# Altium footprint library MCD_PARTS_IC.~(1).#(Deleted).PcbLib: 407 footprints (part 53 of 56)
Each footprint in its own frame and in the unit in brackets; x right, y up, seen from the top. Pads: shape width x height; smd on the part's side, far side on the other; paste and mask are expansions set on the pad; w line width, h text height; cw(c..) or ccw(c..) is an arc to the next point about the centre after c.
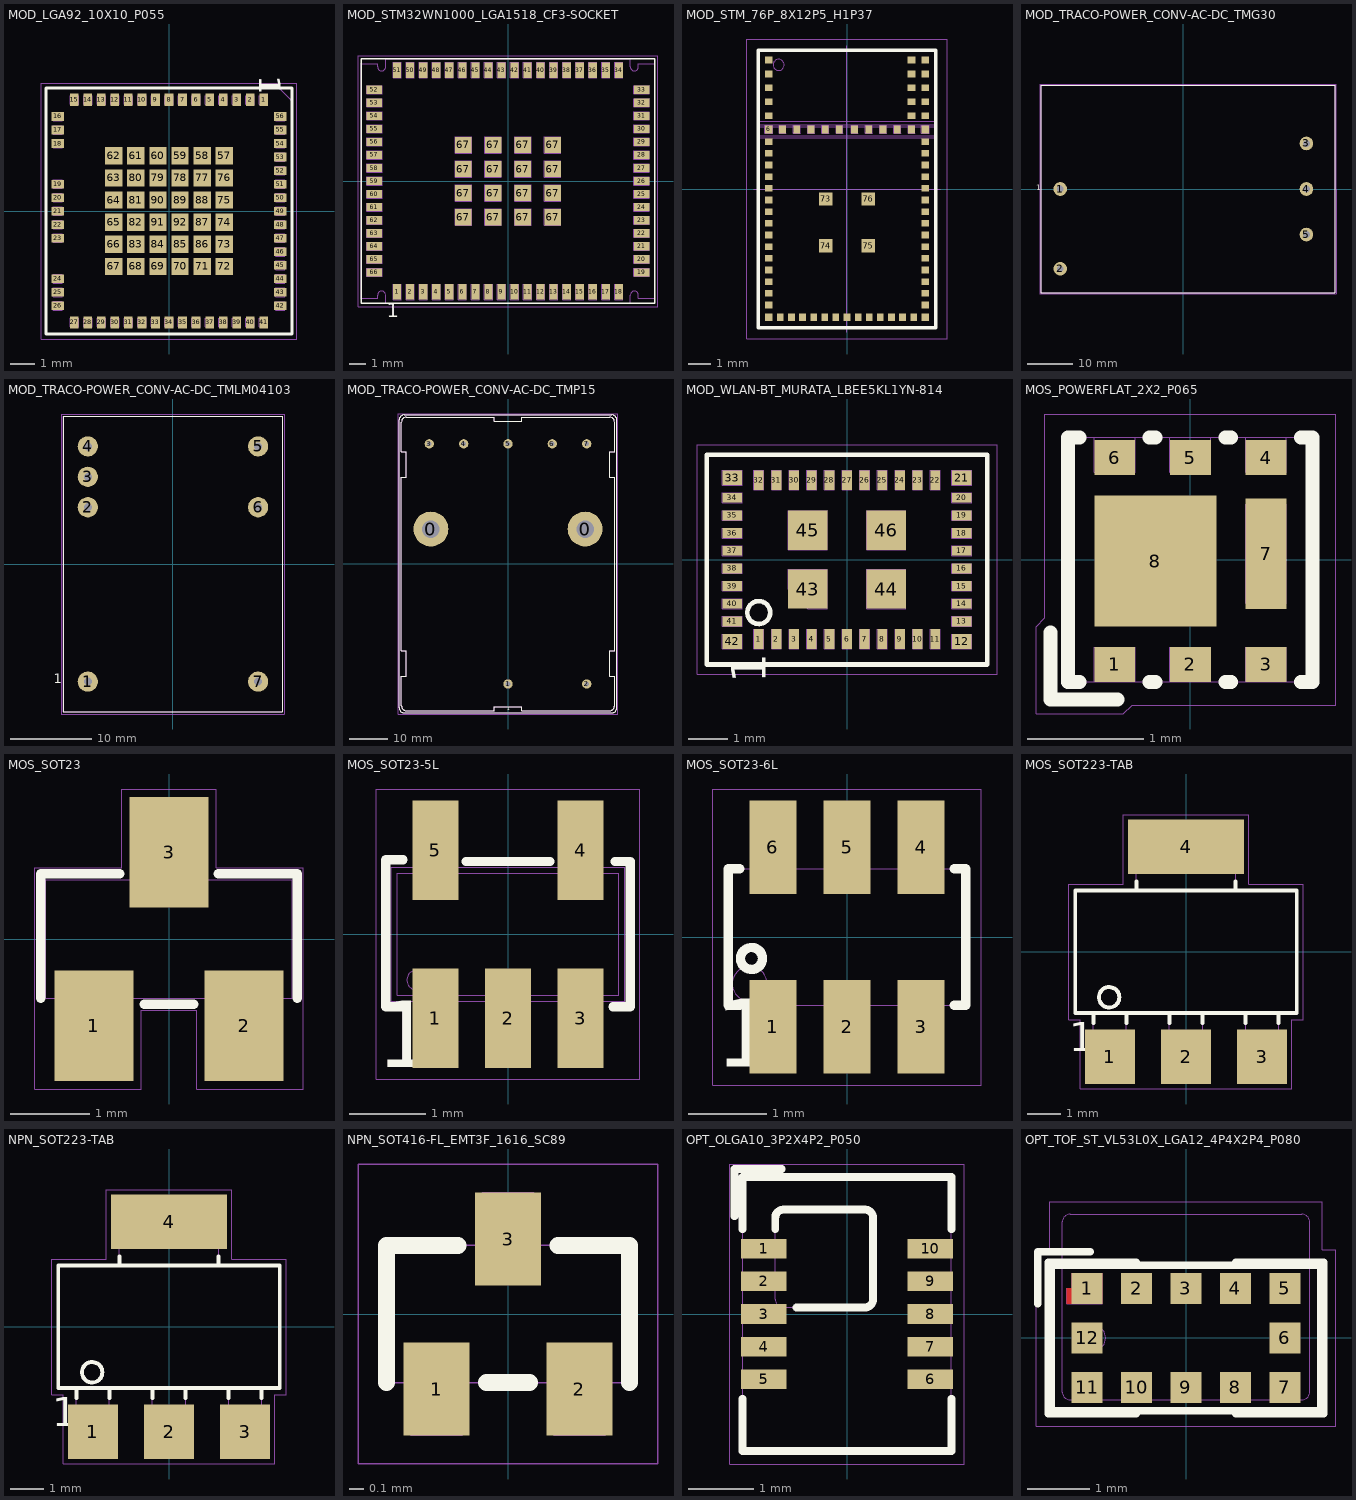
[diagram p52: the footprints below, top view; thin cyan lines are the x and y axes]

## MOD_LGA92_10X10_P055 [mm] "MCD-02403"
height 1.62
pads (92):
  rect 0.35x0.5 smd mask+0.05: 1(3.85,4.525) 2(3.3,4.525) 3(2.75,4.525) 4(2.2,4.525) 5(1.65,4.525) 6(1.1,4.525) 7(0.55,4.525) 8(0,4.525) 9(-0.55,4.525) 10(-1.1,4.525) 11(-1.65,4.525) 12(-2.2,4.525) 13(-2.75,4.525) 14(-3.3,4.525) 15(-3.85,4.525) 27(-3.85,-4.525) 28(-3.3,-4.525) 29(-2.75,-4.525) 30(-2.2,-4.525) 31(-1.65,-4.525) 32(-1.1,-4.525) 33(-0.55,-4.525) 34(0,-4.525) 35(0.55,-4.525) 36(1.1,-4.525) 37(1.65,-4.525) 38(2.2,-4.525) 39(2.75,-4.525) 40(3.3,-4.525) 41(3.85,-4.525)
  rect 0.5x0.35 smd mask+0.05: 16(-4.525,3.85) 17(-4.525,3.3) 18(-4.525,2.75) 19(-4.525,1.1) 20(-4.525,0.55) 21(-4.525,0) 22(-4.525,-0.55) 23(-4.525,-1.1) 24(-4.525,-2.75) 25(-4.525,-3.3) 26(-4.525,-3.85) 42(4.525,-3.85) 43(4.525,-3.3) 44(4.525,-2.75) 45(4.525,-2.2) 46(4.525,-1.65) 47(4.525,-1.1) 48(4.525,-0.55) 49(4.525,0) 50(4.525,0.55) 51(4.525,1.1) 52(4.525,1.65) 53(4.525,2.2) 54(4.525,2.75) 55(4.525,3.3) 56(4.525,3.85)
  rect 0.7x0.7 smd mask+0.05: 57(2.25,2.25) 58(1.35,2.25) 59(0.45,2.25) 60(-0.45,2.25) 61(-1.35,2.25) 62(-2.25,2.25) 63(-2.25,1.35) 64(-2.25,0.45) 65(-2.25,-0.45) 66(-2.25,-1.35) 67(-2.25,-2.25) 68(-1.35,-2.25) 69(-0.45,-2.25) 70(0.45,-2.25) 71(1.35,-2.25) 72(2.25,-2.25) 73(2.25,-1.35) 74(2.25,-0.45) 75(2.25,0.45) 76(2.25,1.35) 77(1.35,1.35) 78(0.45,1.35) 79(-0.45,1.35) 80(-1.35,1.35) 81(-1.35,0.45) 82(-1.35,-0.45) 83(-1.35,-1.35) 84(-0.45,-1.35) 85(0.45,-1.35) 86(1.35,-1.35) 87(1.35,-0.45) 88(1.35,0.45) 89(0.45,0.45) 90(-0.45,0.45) 91(-0.45,-0.45) 92(0.45,-0.45)
Top Overlay:
  lines w0.12: -5,-5 5,-5 5,5 -5,5 -5,-5
  text "1" at 3.375,5.5 h1.5
M14-Top Assembly:
  drawing of 373 lines, arcs and shapes, not listed
  text "92" at 0.095,-0.73 h0.85
  text "91" at -0.835,-0.73 h0.85
  text "90" at -0.815,0.16 h0.85
  text "89" at 0.15,0.15 h0.85
  text "86" at 0.95,-1.625 h0.85
  text "83" at -1.755,-1.64 h0.85
  text "80" at -1.725,1.09 h0.85
  text "77" at 1.05,1.05 h0.85
  text "72" at 1.85,-2.535 h0.85
  text "67" at -2.615,-2.52 h0.85
  text "62" at -2.625,2 h0.85
  text "57" at 1.88,1.965 h0.85
  text "'.Designator'" at -2,3 h0.75
  text "1" at 3.715,4.29 h0.85
  text "15" at -4.285,4.26 h0.85
  text "16" at -4.865,3.59 h0.85
  text "26" at -4.875,-4.135 h0.85
  text "27" at -4.255,-4.805 h0.85
  text "41" at 3.54,-4.815 h0.85
  text "42" at 4.055,-4.145 h0.85
  text "56" at 4.13,3.58 h0.85
M16-Top Courtyard:
  lines w0.01: -5.2,-5.2 5.2,-5.2 5.2,5.2 -5.2,5.2 -5.2,-5.2
3D body: height 1.62, standoff 0, extent -5,-5 5,5
3D body: height 1.63, standoff 1.62, extent 4.156,4.106 4.654,4.605

## MOD_STM32WN1000_LGA1518_CF3-SOCKET [mm]
height 1
pads (82):
  rect 0.5x0.95 smd mask+0.05: 1(-6.8,-6.8) 2(-6,-6.8) 3(-5.2,-6.8) 4(-4.4,-6.8) 5(-3.6,-6.8) 6(-2.8,-6.8) 7(-2,-6.8) 8(-1.2,-6.8) 9(-0.4,-6.8) 10(0.4,-6.8) 11(1.2,-6.8) 12(2,-6.8) 13(2.8,-6.8) 14(3.6,-6.8) 15(4.4,-6.8) 16(5.2,-6.8) 17(6,-6.8) 18(6.8,-6.8) 34(6.8,6.8) 35(6,6.8) 36(5.2,6.8) 37(4.4,6.8) 38(3.6,6.8) 39(2.8,6.8) 40(2,6.8) 41(1.2,6.8) 42(0.4,6.8) 43(-0.4,6.8) 44(-1.2,6.8) 45(-2,6.8) 46(-2.8,6.8) 47(-3.6,6.8) 48(-4.4,6.8) 49(-5.2,6.8) 50(-6,6.8) 51(-6.8,6.8)
  rect 0.95x0.5 smd mask+0.05: 19(8.2,-5.6) 20(8.2,-4.8) 21(8.2,-4) 22(8.2,-3.2) 23(8.2,-2.4) 24(8.2,-1.6) 25(8.2,-0.8) 26(8.2,0) 27(8.2,0.8) 28(8.2,1.6) 29(8.2,2.4) 30(8.2,3.2) 31(8.2,4) 32(8.2,4.8) 33(8.2,5.6) 52(-8.2,5.6) 53(-8.2,4.8) 54(-8.2,4) 55(-8.2,3.2) 56(-8.2,2.4) 57(-8.2,1.6) 58(-8.2,0.8) 59(-8.2,0) 60(-8.2,-0.8) 61(-8.2,-1.6) 62(-8.2,-2.4) 63(-8.2,-3.2) 64(-8.2,-4) 65(-8.2,-4.8) 66(-8.2,-5.6)
  rect 1x1 smd mask+0.05: 67(-2.737,-2.213) 67(-2.737,-0.737) 67(-2.737,0.737) 67(-2.737,2.213) 67(-0.912,-2.213) 67(-0.912,-0.737) 67(-0.912,0.737) 67(-0.912,2.213) 67(0.913,-2.213) 67(0.913,-0.737) 67(0.913,0.737) 67(0.913,2.213) 67(2.738,-2.213) 67(2.738,-0.737) 67(2.738,0.737) 67(2.738,2.213)
Top Overlay:
  lines w0.1: -9,-7.5 9,-7.5 9,7.5 -9,7.5 -9,-7.5
  text "1" at -7.45,-8.675 h1.5
M14-Top Assembly:
  drawing of 352 lines, arcs and shapes, not listed
  text "'.Designator'" at -2,-0.5 h0.75
  text "66" at -8.6,-5.9 h1
  text "52" at -8.65,5.275 h1
  text "51" at -7.2,6.5 h1
  text "34" at 6.375,6.525 h1
  text "33" at 8.5,5.2 h1
  text "19" at 8.475,-6.075 h1
  text "18" at 6.4,-7.125 h1
  text "1" at -6.95,-7.125 h1
M16-Top Courtyard:
  lines w0.01: -9.2,-7.7 -9.2,7.7 9.2,7.7 9.2,-7.7 -9.2,-7.7
3D body "RM5100_S.step": height 1.8, standoff 0.01, extent -9,-7.5 9,7.5

## MOD_STM_76P_8X12P5_H1P37 [mm] "MCD-03538"
height 1.4
pads (76):
  rect 0.35x0.3 smd mask+0.04: 1(-3.525,5.803) 2(-3.525,5.178) 3(-3.525,4.553) 4(-3.525,3.928) 5(-3.525,3.303) 7(-3.525,2.128) 8(-3.525,1.603) 9(-3.525,1.078) 10(-3.525,0.555) 11(-3.525,0.028) 12(-3.525,-0.497) 13(-3.525,-1.022) 14(-3.525,-1.547) 15(-3.525,-2.072) 16(-3.525,-2.597) 17(-3.525,-3.122) 18(-3.525,-3.647) 19(-3.525,-4.172) 20(-3.525,-4.697) 21(-3.525,-5.222) 37(3.525,-5.222) 38(3.525,-4.697) 39(3.525,-4.172) 40(3.525,-3.647) 41(3.525,-3.122) 42(3.525,-2.597) 43(3.525,-2.072) 44(3.525,-1.547) 45(3.525,-1.022) 46(3.525,-0.497) 47(3.525,0.028) 48(3.525,0.555) 49(3.525,1.078) 50(3.525,1.603) 51(3.525,2.128) 53(3.525,3.303) 54(3.525,3.928) 55(3.525,4.553) 56(3.525,5.178) 57(3.525,5.803) 58(2.9,5.803) 59(2.9,5.178) 60(2.9,4.553) 61(2.9,3.928) 62(2.9,3.303)
  rect 0.35x0.35 smd mask+0.04: 6(-3.525,2.678) 22(-3.525,-5.772) 36(3.525,-5.772) 52(3.525,2.678)
  rect 0.3x0.35 smd mask+0.04: 23(-3,-5.772) 24(-2.5,-5.772) 25(-2,-5.772) 26(-1.5,-5.772) 27(-1,-5.772) 28(-0.5,-5.772) 29(0,-5.772) 30(0.5,-5.772) 31(1,-5.772) 32(1.5,-5.772) 33(2,-5.772) 34(2.5,-5.772) 35(3,-5.772) 63(2.9,2.678) 64(2.258,2.678) 65(1.618,2.678) 66(0.978,2.678) 67(0.338,2.678) 68(-0.342,2.678) 69(-0.982,2.678) 70(-1.622,2.678) 71(-2.262,2.678) 72(-2.9,2.678)
  rect 0.6x0.6 smd mask+0.04: 73(-0.95,-0.447) 74(-0.95,-2.547) 75(0.95,-2.547) 76(0.95,-0.447)
Top Overlay:
  lines w0.15: -4,-6.25 4,-6.25 4,6.25 -4,6.25 -4,-6.25
Bottom Assembly:
  lines w0.01: -3.053,2.5 -2.752,2.85 ; -2.752,2.5 -3.052,2.5 -3.052,2.85 ; -2.752,2.5 -3.052,2.85 ; -2.752,2.55 -2.752,2.85 ; -2.412,2.5 -2.112,2.85 ; -2.112,2.5 -2.412,2.85 ; -1.773,2.5 -1.472,2.85 ; -1.472,2.5 -1.772,2.85 ; -1.132,2.5 -0.832,2.85 ; -0.832,2.5 -1.132,2.85 ; -0.493,2.5 -0.192,2.85 ; -0.192,2.5 -0.492,2.85 ; 0.188,2.5 0.488,2.85 ; 0.488,2.5 0.188,2.85 ; 0.827,2.5 1.128,2.85 ; 1.128,2.5 0.828,2.85 ; 1.468,2.5 1.768,2.85 ; 1.768,2.5 1.468,2.85 ; 2.107,2.5 2.408,2.85 ; 2.408,2.5 2.108,2.85 ; 2.748,2.5 3.048,2.85 ; 3.048,2.5 2.748,2.85 ; -3.052,2.85 -2.752,2.85 ; -2.412,2.85 -2.112,2.85 ; -2.412,2.85 -2.412,2.5 -2.112,2.5 -2.112,2.85 ; -1.772,2.85 -1.472,2.85 ; -1.772,2.85 -1.772,2.5 -1.472,2.5 -1.472,2.85 ; -1.132,2.85 -0.832,2.85 ; -1.132,2.85 -1.132,2.5 -0.832,2.5 -0.832,2.85 ; -0.492,2.85 -0.192,2.85 ; -0.492,2.85 -0.492,2.5 -0.192,2.5 -0.192,2.85 ; 0.188,2.85 0.488,2.85 ; 0.188,2.85 0.188,2.5 0.488,2.5 0.488,2.85 ; 0.828,2.85 1.128,2.85 ; 0.828,2.85 0.828,2.5 1.128,2.5 1.128,2.85 ; 1.468,2.85 1.768,2.85 ; 1.468,2.85 1.468,2.5 1.768,2.5 1.768,2.85 ; 2.108,2.85 2.408,2.85 ; 2.108,2.85 2.108,2.5 2.408,2.5 2.408,2.85 ; 2.748,2.85 3.048,2.85 ; 2.748,2.85 2.748,2.5 3.048,2.5 3.048,2.85 ; -3.702,2.5 -3.352,2.5 -3.352,2.85 -3.702,2.85 -3.702,2.5 ; 3.348,2.5 3.698,2.5 3.698,2.85 3.348,2.85 3.348,2.5
Top 3D Body:
  lines w0.01: -4.202,0 4.198,0 ; -0.002,-6.45 -0.002,6.45
Bottom 3D Body:
  circle w0.005: c0.948,-2.63 r0.002
  circle w0.005: c-0.952,-2.63 r0.002
  circle w0.005: c3.603,5.8 r0.002
  circle w0.005: c3.603,3.3 r0.002
  circle w0.005: c-3.607,-5.225 r0.002
  circle w0.005: c-3.607,-5.775 r0.002
  circle w0.005: c-3.002,-5.855 r0.002
  circle w0.005: c-3.527,-5.855 r0.002
  circle w0.005: c1.028,-0.45 r0.002
  circle w0.005: c1.028,-2.55 r0.002
  circle w0.005: c3.603,5.8 r0.002
  circle w0.005: c3.998,-6.25 r0.002
  circle w0.005: c-4.002,-6.25 r0.002
  circle w0.005: c3.998,-6.25 r0.002
  circle w0.005: c3.602,5.8 r0.002
  circle w0.005: c3.602,-5.775 r0.002
  circle w0.005: c-1.002,-5.855 r0.002
  circle w0.005: c-0.502,-5.855 r0.002
  circle w0.005: c3.603,-1.55 r0.002
  circle w0.005: c3.603,-2.075 r0.002
  circle w0.005: c-3.527,5.88 r0.002
  circle w0.005: c3.523,5.88 r0.002
  circle w0.005: c-1.032,-0.45 r0.002
  circle w0.005: c-0.953,-0.37 r0.002
  circle w0.005: c-3.527,-5.855 r0.002
  circle w0.005: c3.523,-5.855 r0.002
  circle w0.005: c3.603,2.675 r0.002
  circle w0.005: c3.603,2.125 r0.002
  circle w0.005: c3.523,5.88 r0.002
  circle w0.005: c2.898,5.88 r0.002
  circle w0.005: c2.818,5.175 r0.002
  circle w0.005: c2.818,5.8 r0.002
M14-Top Assembly:
  circle w0.01: c-3.078,5.587 r0.25
  lines w0.01: -4.004,-6.25 3.997,-6.25 ; -4,-6.25 -4,6.253 4,6.253 4,-6.25 ; -4,2.3 4,2.3 ; -4,2.4 4,2.4 ; -4,2.8 4,2.8 ; -4,2.9 4,2.9 ; -4,3.06 4,3.06
  text ".'Designator'" at -1.777,1.358 h0.75
M16-Top Courtyard:
  lines w0.01: -4.5,-6.75 -4.5,6.75 4.5,6.75 4.5,-6.75 -4.5,-6.75
3D body: height 1.4, standoff 0, extent -4,2.3 4,2.4
3D body: height 1.4, standoff 0, extent -4,2.8 4,2.9
3D body: height 1.25, standoff 0, extent -4,2.4 4,2.8
3D body: height 1.4, standoff 0, extent -4.004,-6.25 3.996,2.3
3D body: height 1.4, standoff 0, extent -4,2.9 4,6.243
3D body: height 1.41, standoff 0.05, extent -3.298,5.367 -2.858,5.807

## MOD_TRACO-POWER_CONV-AC-DC_TMG30 [mm] "MCD-03101"
height 23.5
pads (5):
  round 3 hole 1.5 mask+0: 1(-27,0) 2(-27,-17.5) 3(27,10) 4(27,0) 5(27,-10)
Top Overlay:
  lines w0.12: -31.25,-22.75 33.25,-22.75 33.25,22.75 -31.25,22.75 -31.25,-22.75
  text "1" at -32.325,-0.7 h2
M14-Top Assembly:
  lines w0.01: -31.25,-22.75 -31.25,22.75 33.25,22.75 33.25,-22.75 -31.25,-22.75
  text "5" at 26.65,-10.555 h2
  text "4" at 26.7,-0.45 h2
  text "3" at 26.575,9.52 h2
  text "2" at -27.302,-18 h2
  text "1" at -27.25,-0.425 h2
  text "'.Designator'" at -2,-0.5 h0.75
M16-Top Courtyard:
  lines w0.01: -31.5,-23 -31.5,23 33.5,23 33.5,-23 -31.5,-23
3D body: height 0.25, standoff 0, extent -27,0 -26.746,0.254
3D body "tmg30_3d_drawing.stp": height 22.1, standoff -7.9, extent -31.6,-22.375 33,23.025

## MOD_TRACO-POWER_CONV-AC-DC_TMLM04103 [mm] "MCD-03102"
height 17.1
pads (7):
  round 2.5 hole 1 mask+0: 1(-10.5,-14.5) 2(-10.5,7) 3(-10.5,10.75) 4(-10.5,14.5) 5(10.5,14.5) 6(10.5,7) 7(10.5,-14.5)
Top Overlay:
  lines w0.12: -13.5,-18.25 13.5,-18.25 13.5,18.25 -13.5,18.25 -13.5,-18.25
  text "1" at -14.725,-15.15 h2
M14-Top Assembly:
  lines w0.01: -13.5,-18.25 -13.5,18.25 13.5,18.25 13.5,-18.25 -13.5,-18.25
  text "'.Designator'" at -2,-0.5 h0.75
  text "1" at -10.925,-15.1 h2
  text "2" at -10.927,6.375 h2
  text "3" at -10.925,10.12 h2
  text "4" at -10.925,13.95 h2
  text "5" at 10.4,13.97 h2
  text "6" at 10.4,6.395 h2
  text "7" at 10.4,-15.1 h2
M16-Top Courtyard:
  lines w0.01: -13.75,-18.5 -13.75,18.5 13.75,18.5 13.75,-18.5 -13.75,-18.5
3D body: height 0.25, standoff 0, extent -10.541,14.645 -10.287,14.899
3D body "tmlm04_single_3d_drawing.stp": height 17.8, standoff -3.7, extent -13.755,-18.313 13.748,18.69

## MOD_TRACO-POWER_CONV-AC-DC_TMP15 [mm] "MCD-03103"
height 20.27
pads (9):
  round 9 hole 4.5 mask+0.05: 0(-19.9,9) 0(19.9,9)
  round 2.4 hole 1.2 mask+0.05: 1(0,-31) 2(20.32,-31) 3(-20.32,31) 4(-11.43,31) 5(0,31) 6(11.43,31) 7(20.32,31)
Top Overlay:
  lines w0.12: -28.065,37.1 -28.065,37.185 ; -28.065,37.185 cw(c-26.795,37.185) -26.795,38.455 26.795,38.455 cw(c26.795,37.185) 28.065,37.185 28.065,-37.185 cw(c26.795,-37.185) 26.795,-38.455 -26.795,-38.455 cw(c-26.795,-37.185) -28.065,-37.185 -28.065,37.185 ; -27.5,-36.63 ccw(c-26.23,-36.63) -26.23,-37.9 -3.5,-37.9 -3.5,-36.875 3.5,-36.875 3.5,-37.9 26.23,-37.9 ccw(c26.23,-36.63) 27.5,-36.63 27.5,-29 26.3,-29 26.3,-22.4 27.5,-22.4 27.5,22.4 26.3,22.4 26.3,29 27.5,29 27.5,36.63 ccw(c26.23,36.63) 26.23,37.9 3.5,37.9 3.5,36.875 -3.5,36.875 -3.5,37.9 -26.23,37.9 ccw(c-26.23,36.63) -27.5,36.63 -27.5,29 -26.3,29 -26.3,22.4 -27.5,22.4 -27.5,-22.4 -26.3,-22.4 -26.3,-29 -27.5,-29 -27.5,-36.63
  text "1" at -0.25,-38.175 h1.5
M14-Top Assembly:
  circle w0.01: c-20.32,31 r0.5
  circle w0.01: c11.43,31 r0.5
  circle w0.01: c-11.43,31 r0.5
  circle w0.01: c0,31 r0.5
  circle w0.01: c20.32,31 r0.5
  circle w0.01: c0,-31 r0.5
  circle w0.01: c20.32,-31 r0.5
  circle w0.01: c19.9,9 r2
  circle w0.01: c-19.9,9 r2
  lines w0.01: -28.065,37.1 -28.065,37.185 ; -28.065,37.185 cw(c-26.795,37.185) -26.795,38.455 26.795,38.455 cw(c26.795,37.185) 28.065,37.185 28.065,-37.185 cw(c26.795,-37.185) 26.795,-38.455 -26.795,-38.455 cw(c-26.795,-37.185) -28.065,-37.185 -28.065,37.185 ; -27.5,-36.63 ccw(c-26.23,-36.63) -26.23,-37.9 -3.5,-37.9 -3.5,-36.875 3.5,-36.875 3.5,-37.9 26.23,-37.9 ccw(c26.23,-36.63) 27.5,-36.63 27.5,-29 26.3,-29 26.3,-22.4 27.5,-22.4 27.5,22.4 26.3,22.4 26.3,29 27.5,29 27.5,36.63 ccw(c26.23,36.63) 26.23,37.9 3.5,37.9 3.5,36.875 -3.5,36.875 -3.5,37.9 -26.23,37.9 ccw(c-26.23,36.63) -27.5,36.63 -27.5,29 -26.3,29 -26.3,22.4 -27.5,22.4 -27.5,-22.4 -26.3,-22.4 -26.3,-29 -27.5,-29 -27.5,-36.63
  text "7" at 20.05,31.9 h2
  text "6" at 11.075,31.92 h2
  text "5" at -0.375,31.92 h2
  text "4" at -11.9,31.9 h2
  text "3" at -20.65,31.92 h2
  text "2" at 19.923,-30.1 h2
  text "1" at -0.3,-30.1 h2
  text "'.Designator'" at -2,-0.5 h0.75
M16-Top Courtyard:
  lines w0.01: -28.325,-38.75 -28.325,38.7 28.325,38.7 28.325,-38.75 -28.325,-38.75
3D body "tmp15_pcb_dual_symmetric_3d_drawing.stp": height 19.5, standoff -6, extent -27,-37 27,37

## MOD_WLAN-BT_MURATA_LBEE5KL1YN-814 [mm] "MCD-03465"
height 1.1
pads (46):
  rect 0.25x0.5 smd mask+0.05: 1(-2.25,-2.025) 2(-1.8,-2.025) 3(-1.35,-2.025) 4(-0.9,-2.025) 5(-0.45,-2.025) 6(0,-2.025) 7(0.45,-2.025) 8(0.9,-2.025) 9(1.35,-2.025) 10(1.8,-2.025) 11(2.25,-2.025) 22(2.25,2.025) 23(1.8,2.025) 24(1.35,2.025) 25(0.9,2.025) 26(0.45,2.025) 27(0,2.025) 28(-0.45,2.025) 29(-0.9,2.025) 30(-1.35,2.025) 31(-1.8,2.025) 32(-2.25,2.025)
  rect 0.5x0.375 smd mask+0.05: 12(2.925,-2.087) 21(2.925,2.087) 33(-2.925,2.087) 42(-2.925,-2.087)
  rect 0.5x0.25 smd mask+0.05: 13(2.925,-1.575) 14(2.925,-1.125) 15(2.925,-0.675) 16(2.925,-0.225) 17(2.925,0.225) 18(2.925,0.675) 19(2.925,1.125) 20(2.925,1.575) 34(-2.925,1.575) 35(-2.925,1.125) 36(-2.925,0.675) 37(-2.925,0.225) 38(-2.925,-0.225) 39(-2.925,-0.675) 40(-2.925,-1.125) 41(-2.925,-1.575)
  rect 1x1 smd mask+0.05: 43(-1,-0.75) 44(1,-0.75) 45(-1,0.75) 46(1,0.75)
Top Overlay:
  circle w0.12: c-2.25,-1.35 r0.292
  lines w0.12: -3.575,-2.675 3.575,-2.675 3.575,2.675 -3.575,2.675 -3.575,-2.675
  text "1" at -1.775,-3.15 h1.5
M14-Top Assembly:
  drawing of 190 lines, arcs and shapes, not listed
  text "1" at -2.325,-2.175 h0.5
  text "42" at -3.15,-2.25 h0.5
  text "12" at 2.725,-2.25 h0.5
  text "21" at 2.725,1.925 h0.5
  text "33" at -3.15,1.925 h0.5
  text "45" at -1.225,0.6 h0.5
  text "46" at 0.775,0.6 h0.5
  text "43" at -1.25,-0.925 h0.5
  text "44" at 0.775,-0.875 h0.5
  text "'.Designator'" at 0,0 h0.75
M16-Top Courtyard:
  lines w0.01: -3.825,-2.925 3.825,-2.925 3.825,2.925 -3.825,2.925 -3.825,-2.925
3D body: height 1.11, standoff 1.1, extent -2.597,-2.274 -1.9,-1.576
3D body: height 1.1, standoff 0, extent -3.575,-2.675 3.575,2.675

## MOS_POWERFLAT_2X2_P065 [mm] "MCD-01028  PowerFLAT, 6-Leads, Body 2.1x2.1mm"
height 0.8
pads (8):
  rect 0.35x0.3 smd mask+0.038: 1(-0.65,-0.9) 2(0,-0.9) 3(0.65,-0.9) 4(0.65,0.875) 5(0,0.875) 6(-0.65,0.875)
  rect 0.35x0.95 smd mask+0.038: 7(0.65,0.05)
  rect 1.05x1.125 smd mask+0.038: 8(-0.3,-0.012)
Top Overlay:
  lines w0.12: -1.2,-0.625 -1.2,-1.2 -0.625,-1.2 ; -0.95,-1.05 -1.05,-1.05 -1.05,1.05 -0.95,1.05 ; -0.35,-1.05 -0.3,-1.05 ; -0.35,1.05 -0.3,1.05 ; 0.3,-1.05 0.35,-1.05 ; 0.3,1.05 0.35,1.05 ; 0.95,-1.05 1.05,-1.05 1.05,1.05 0.95,1.05
M14-Top Assembly:
  lines w0.01: -0.825,-1.05 -0.825,-0.75 -0.475,-0.75 -0.475,-1.05 ; -0.825,1.05 -0.825,0.75 -0.475,0.75 -0.475,1.05 ; -0.175,-1.05 -0.175,-0.75 0.175,-0.75 0.175,-1.05 ; -0.175,1.05 -0.175,0.75 0.175,0.75 0.175,1.05 ; 0.475,-1.05 0.475,-0.75 0.825,-0.75 0.825,-1.05 ; 0.475,1.05 0.475,0.75 0.825,0.75 0.825,1.05 ; -1.05,-1.05 -1.05,1.05 1.05,1.05 1.05,-1.05 -1.05,-1.05 ; -0.75,-0.312 -0.55,-0.513 0.15,-0.513 0.15,0.487 -0.75,0.487 -0.75,-0.312 ; 0.475,-0.375 0.825,-0.375 0.825,0.475 0.475,0.475 0.475,-0.375
  text "8" at -0.375,-0.15 h0.4
  text "6" at -0.75,0.775 h0.4
  text "5" at -0.1,0.775 h0.4
  text "4" at 0.55,0.775 h0.4
  text "7" at 0.575,-0.075 h0.4
  text "3" at 0.575,-1.025 h0.4
  text "2" at -0.075,-1.025 h0.4
  text "1" at -0.7,-1.025 h0.4
  text ".Designator" at -2,-0.5 h0.75
M16-Top Courtyard:
  lines w0.01: -1.325,-1.325 -0.575,-1.325 -0.5,-1.25 1.25,-1.25 1.25,1.25 -1.25,1.25 -1.25,-0.5 -1.325,-0.575 -1.325,-1.325
3D body: height 0.8, standoff 0, extent -1.05,-1.05 1.05,1.05
3D body: height 0.81, standoff 0.8, extent -0.924,-0.925 -0.625,-0.625

## MOS_SOT23 [mm]
height 1.1
pads (3):
  rect 1x1.4 smd mask+0.05: 1(-0.95,-1.1) 2(0.95,-1.1) 3(0,1.1)
Top Overlay:
  lines w0.12: -1.625,-0.75 -1.625,0.825 -0.624,0.825 ; -0.312,-0.825 0.312,-0.825 ; 0.624,0.825 1.625,0.825 1.625,-0.75
M14-Top Assembly:
  lines w0.01: -1.56,-0.75 -1.56,0.75 1.56,0.75 1.56,-0.75 -1.56,-0.75 ; -1.275,-1.025 -0.675,-1.025 -0.675,-0.75 -1.275,-0.75 -1.275,-1.025 ; -0.25,0.75 0.325,0.75 0.325,1.05 -0.25,1.05 -0.25,0.75 ; 0.65,-1.025 1.25,-1.025 1.25,-0.75 0.65,-0.75 0.65,-1.025
  text "'.Designator'" at -2,-0.5 h0.75
M16-Top Courtyard:
  lines w0.01: -1.7,-1.9 -0.35,-1.9 -0.35,-0.9 0.35,-0.9 0.35,-1.9 1.7,-1.9 1.7,0.9 0.6,0.9 0.6,1.9 -0.6,1.9 -0.6,0.9 -1.7,0.9 -1.7,-1.9
3D body: height 1.1, standoff 0, extent -1.559,-0.749 1.559,0.749
3D body "SOT23-3_TO-236AB.STEP": height 1.09, standoff 0, extent -1.5,-1.25 1.5,1.25

## MOS_SOT23-5L [mm]
height 1.45
pads (5):
  rect 0.6x1.3 smd mask+0.05: 1(-0.95,-1.1) 2(0,-1.1) 3(0.95,-1.1) 4(0.95,1.1) 5(-0.95,1.1)
Top Overlay:
  lines w0.12: -1.375,0.975 -1.6,0.975 -1.6,-0.95 -1.372,-0.95 ; -0.55,0.95 0.55,0.95 ; 1.372,-0.95 1.6,-0.95 1.6,0.95 1.4,0.95
  text "1" at -1.725,-2.025 h1.5
M14-Top Assembly:
  circle w0.01: c-1.2,-0.6 r0.125
  lines w0.01: -1.15,-0.875 -1.15,-1.5 -0.75,-1.5 -0.75,-0.875 ; -1.15,0.875 -1.15,1.5 -0.75,1.5 -0.75,0.875 ; -0.2,-0.875 -0.2,-1.5 0.2,-1.5 0.2,-0.875 ; 0.75,-0.875 0.75,-1.5 1.15,-1.5 1.15,-0.875 ; 0.75,0.875 0.75,1.5 1.15,1.5 1.15,0.875 ; -1.525,-0.875 1.525,-0.875 1.525,0.875 -1.525,0.875 -1.525,-0.875 ; -1.45,-0.8 -1.45,0.8 1.45,0.8 1.45,-0.8 -1.45,-0.8
  text "'.Designator'" at -2,-0.5 h0.75
M16-Top Courtyard:
  lines w0.01: -1.725,-1.9 1.725,-1.9 1.725,1.9 -1.725,1.9 -1.725,-1.9
3D body: height 1.45, standoff 0, extent -1.524,-0.874 1.524,0.874
3D body "SOT23-5L.STEP": height 1.1, standoff 0, extent -1.5,-1.25 1.5,1.25

## MOS_SOT23-6L [mm]
height 1.25
pads (6):
  rect 0.6x1.2 smd mask+0.05: 1(-0.95,-1.15) 2(0,-1.15) 3(0.95,-1.15) 4(0.95,1.15) 5(0,1.15) 6(-0.95,1.15)
Top Overlay:
  circle w0.12: c-1.225,-0.275 r0.141
  lines w0.12: -1.375,-0.875 -1.525,-0.875 -1.525,0.875 -1.375,0.875 ; 1.375,-0.875 1.525,-0.875 1.525,0.875 1.375,0.875
  text "1" at -1.69,-1.95 h1.5
M14-Top Assembly:
  circle w0.01: c-1.25,-0.6 r0.224
  lines w0.01: -1.2,-0.875 -1.2,-1.5 -0.7,-1.5 -0.7,-0.875 ; -1.2,0.875 -1.2,1.5 -0.7,1.5 -0.7,0.875 ; -0.25,-0.875 -0.25,-1.5 0.25,-1.5 0.25,-0.875 ; -0.25,0.875 -0.25,1.5 0.25,1.5 0.25,0.875 ; 0.7,-0.875 0.7,-1.5 1.2,-1.5 1.2,-0.875 ; 0.7,0.875 0.7,1.5 1.2,1.5 1.2,0.875 ; -1.525,-0.875 -1.525,0.875 1.525,0.875 1.525,-0.875 -1.525,-0.875
  text "2" at -0.15,-1.425 h0.75
  text "3" at 0.78,-1.43 h0.75
  text "1" at -1.05,-1.425 h0.75
  text "6" at -1.1,0.925 h0.75
  text "5" at -0.15,0.925 h0.75
  text "4" at 0.78,0.91 h0.75
  text "'.Designator'" at -2,-0.5 h0.75
M16-Top Courtyard:
  lines w0.01: -1.725,-1.9 -1.725,1.9 1.725,1.9 1.725,-1.9 -1.725,-1.9
3D body "SOT23-6.STEP": height 1.3, standoff 0, extent -1.5,-1.5 1.5,1.5
3D body: height 1.25, standoff 0, extent -1.524,-0.874 1.524,0.874

## MOS_SOT223-TAB [mm]
height 1.8
pads (4):
  rect 1.5x1.65 smd mask+0.05: 1(-2.3,-3.175) 2(0,-3.175) 3(2.3,-3.175)
  rect 3.5x1.65 smd mask+0.05: 4(0,3.175)
Top Overlay:
  circle w0.12: c-2.325,-1.375 r0.309
  lines w0.12: -2.8,-2.15 -2.8,-1.85 -1.8,-1.85 -1.8,-2.15 ; -1.5,2.125 -1.5,1.85 1.5,1.85 1.5,2.125 ; -0.5,-2.15 -0.5,-1.85 0.5,-1.85 0.5,-2.15 ; 1.8,-2.15 1.8,-1.85 2.8,-1.85 2.8,-2.15 ; -3.35,-1.85 -3.35,1.85 3.35,1.85 3.35,-1.85 -3.35,-1.85
  text "1" at -3.525,-3.3 h1.5
M14-Top Assembly:
  circle w0.01: c-2.325,-1.375 r0.285
  lines w0.01: -3.35,-1.85 -3.35,1.85 3.35,1.85 3.35,-1.85 -3.35,-1.85 ; -2.8,-3.65 -1.8,-3.65 -1.8,-1.85 -2.8,-1.85 -2.8,-3.65 ; -1.5,1.85 1.5,1.85 1.5,3.65 -1.5,3.65 -1.5,1.85 ; -0.5,-3.65 0.5,-3.65 0.5,-1.85 -0.5,-1.85 -0.5,-3.65 ; 1.8,-3.65 2.8,-3.65 2.8,-1.85 1.8,-1.85 1.8,-3.65
  text "'.Designator'" at -2,-0.5 h0.75
  text "3" at 1.95,-3.4 h1.5
  text "2" at -0.35,-3.375 h1.5
  text "1" at -2.5,-3.35 h1.5
  text "4" at -0.325,2.375 h1.5
M16-Top Courtyard:
  lines w0.01: -3.55,-2.05 -3.55,2.05 -1.9,2.05 -1.9,4.15 1.9,4.15 1.9,2.05 3.55,2.05 3.55,-2.05 3.2,-2.05 3.2,-4.15 -3.2,-4.15 -3.2,-2.05 -3.55,-2.05
3D body "SOT223.STEP": height 1.68, standoff 0, extent -3.25,-3.48 3.25,3.48
3D body: height 1.8, standoff 0, extent -3.349,-1.849 3.349,1.849

## NPN_SOT223-TAB [mm] "MCD-01495"
height 1.65
pads (4):
  rect 1.5x1.65 smd mask+0.05: 1(-2.3,-3.175) 2(0,-3.175) 3(2.3,-3.175)
  rect 3.5x1.65 smd mask+0.05: 4(0,3.175)
Top Overlay:
  circle w0.12: c-2.325,-1.375 r0.309
  lines w0.12: -2.8,-2.15 -2.8,-1.85 -1.8,-1.85 -1.8,-2.15 ; -1.5,2.125 -1.5,1.85 1.5,1.85 1.5,2.125 ; -0.5,-2.15 -0.5,-1.85 0.5,-1.85 0.5,-2.15 ; 1.8,-2.15 1.8,-1.85 2.8,-1.85 2.8,-2.15 ; -3.35,-1.85 3.35,-1.85 3.35,1.85 -3.35,1.85 -3.35,-1.85
  text "1" at -3.525,-3.3 h1.5
M14-Top Assembly:
  circle w0.01: c-2.325,-1.375 r0.285
  lines w0.01: -3.35,-1.85 3.35,-1.85 3.35,1.85 -3.35,1.85 -3.35,-1.85 ; -2.8,-3.65 -2.8,-1.85 -1.8,-1.85 -1.8,-3.65 -2.8,-3.65 ; -1.5,1.85 -1.5,3.65 1.5,3.65 1.5,1.85 -1.5,1.85 ; -0.5,-3.65 -0.5,-1.85 0.5,-1.85 0.5,-3.65 -0.5,-3.65 ; 1.8,-3.65 1.8,-1.85 2.8,-1.85 2.8,-3.65 1.8,-3.65
  text "4" at -0.325,2.375 h1.5
  text "1" at -2.5,-3.35 h1.5
  text "2" at -0.35,-3.375 h1.5
  text "3" at 1.95,-3.4 h1.5
  text "'.Designator'" at -2,-0.5 h0.75
M16-Top Courtyard:
  lines w0.01: -3.55,-2.05 -3.2,-2.05 -3.2,-4.15 3.2,-4.15 3.2,-2.05 3.55,-2.05 3.55,2.05 1.9,2.05 1.9,4.15 -1.9,4.15 -1.9,2.05 -3.55,2.05 -3.55,-2.05
3D body: height 1.65, standoff 0, extent -3.349,-1.849 3.349,1.849
3D body "SOT223.STEP": height 1.68, standoff 0, extent -3.25,-3.48 3.25,3.48

## NPN_SOT416-FL_EMT3F_1616_SC89 [mm]
height 0.85
pads (3):
  rect 0.46x0.65 smd mask+0.05: 1(-0.5,-0.525) 2(0.5,-0.525) 3(0,0.525)
Top Overlay:
  lines w0.12: -0.85,-0.48 -0.85,0.48 -0.35,0.48 ; -0.15,-0.48 0.15,-0.48 ; 0.35,0.48 0.85,0.48 0.85,-0.48
M14-Top Assembly:
  lines w0.01: -0.68,-0.48 -0.68,-0.85 -0.32,-0.85 -0.32,-0.48 ; -0.18,0.48 -0.18,0.85 0.18,0.85 0.18,0.48 ; 0.32,-0.48 0.32,-0.85 0.68,-0.85 0.68,-0.48 ; -0.85,-0.48 0.85,-0.48 0.85,0.48 -0.85,0.48 -0.85,-0.48
  text "'.Designator'" at -2,-0.5 h0.75
M16-Top Courtyard:
  lines w0.01: -1.05,-1.05 -1.05,1.05 -0.275,1.05 1.05,1.05 1.05,-1.05 -1.05,-1.05
3D body "SOT416-FL_SC-89.STEP": height 0.78, standoff 0, extent -0.85,-0.85 0.85,0.85
3D body: height 0.85, standoff 0, extent -0.855,-0.48 0.855,0.48
3D body: height 0.1, standoff 0, extent -0.183,0.48 0.185,0.847
3D body: height 0.1, standoff 0, extent -0.685,-0.847 -0.317,-0.48
3D body: height 0.1, standoff 0, extent 0.315,-0.847 0.683,-0.48

## OPT_OLGA10_3P2X4P2_P050 [mm]
height 1.455
pads (10):
  rect 0.7x0.3 smd mask+0.05: 1(-1.275,1) 2(-1.275,0.5) 3(-1.275,0) 4(-1.275,-0.5) 5(-1.275,-1) 6(1.275,-1) 7(1.275,-0.5) 8(1.275,0) 9(1.275,0.5) 10(1.275,1)
Top Overlay:
  lines w0.12: -1.725,1.5 -1.725,2.225 -1,2.225 ; -1.6,-1.3 -1.6,-2.1 1.6,-2.1 1.6,-1.3 ; -1.6,1.3 -1.6,2.1 1.6,2.1 1.6,1.3 ; -1.1,1.3 -1.1,1.475 cw(c-0.975,1.475) -0.975,1.6 -0.775,1.6 0.275,1.6 cw(c0.275,1.475) 0.4,1.475 0.4,0.225 cw(c0.275,0.225) 0.275,0.1 -0.775,0.1
M14-Top Assembly:
  lines w0.01: -0.975,1.6 ccw(c-0.975,1.475) -1.1,1.475 -1.1,0.225 ccw(c-0.975,0.225) -0.975,0.1 0.275,0.1 ccw(c0.275,0.225) 0.4,0.225 0.4,1.475 ccw(c0.275,1.475) 0.275,1.6 -0.975,1.6 ; -0.975,1.6 -0.975,1.6 ; -1.6,-2.1 1.6,-2.1 1.6,2.1 -1.6,2.1 -1.6,-2.1 ; -1.45,-1.125 -1.1,-1.125 -1.1,-0.875 -1.45,-0.875 -1.45,-1.125 ; -1.45,-0.625 -1.1,-0.625 -1.1,-0.375 -1.45,-0.375 -1.45,-0.625 ; -1.45,-0.125 -1.1,-0.125 -1.1,0.125 -1.45,0.125 -1.45,-0.125 ; -1.45,0.375 -1.1,0.375 -1.1,0.625 -1.45,0.625 -1.45,0.375 ; -1.45,0.875 -1.1,0.875 -1.1,1.125 -1.45,1.125 -1.45,0.875 ; 1.1,-1.125 1.45,-1.125 1.45,-0.875 1.1,-0.875 1.1,-1.125 ; 1.1,-0.625 1.45,-0.625 1.45,-0.375 1.1,-0.375 1.1,-0.625 ; 1.1,-0.125 1.45,-0.125 1.45,0.125 1.1,0.125 1.1,-0.125 ; 1.1,0.375 1.45,0.375 1.45,0.625 1.1,0.625 1.1,0.375 ; 1.1,0.875 1.45,0.875 1.45,1.125 1.1,1.125 1.1,0.875
  text "'.Designator'" at -2,-0.5 h0.75
  text "1" at -1.334,0.839 h0.5
  text "5" at -1.381,-1.155 h0.5
  text "6" at 1.169,-1.158 h0.5
  text "10" at 1.061,0.842 h0.5
M16-Top Courtyard:
  lines w0.01: -1.8,-2.3 -1.8,2.3 1.8,2.3 1.8,-2.3 -1.8,-2.3
3D body: height 0.05, standoff 0, extent 1.1,-1.125 1.45,-0.875
3D body: height 0.05, standoff 0, extent -1.45,-0.125 -1.1,0.125
3D body: height 0.05, standoff 0, extent -1.45,-0.625 -1.1,-0.375
3D body: height 0.05, standoff 0, extent -1.45,-1.125 -1.1,-0.875
3D body: height 0.05, standoff 0, extent 1.1,0.375 1.45,0.625
3D body: height 0.05, standoff 0, extent 1.1,0.875 1.45,1.125
3D body: height 0.05, standoff 0, extent -1.45,0.875 -1.1,1.125
3D body: height 0.05, standoff 0, extent -1.45,0.375 -1.1,0.625
3D body: height 0.05, standoff 0, extent 1.1,-0.625 1.45,-0.375
3D body: height 0.05, standoff 0, extent 1.1,-0.125 1.45,0.125
3D body: height 1.46, standoff 0.05, extent -1.6,-2.1 1.6,2.1
3D body: height 1.2, standoff 0.05, extent -1.1,0.1 0.4,1.6
3D body: height 1.46, standoff 1.15, extent -1.1,0.1 0.4,1.6

## OPT_TOF_ST_VL53L0X_LGA12_4P4X2P4_P080 [mm] "MCD-01730"
height 1.1
pads (12):
  rect 0.5x0.5 smd mask+0.05: 1(-1.6,0.8) 2(-0.8,0.8) 3(0,0.8) 4(0.8,0.8) 5(1.6,0.8) 6(1.6,0) 7(1.6,-0.8) 8(0.8,-0.8) 9(0,-0.8) 10(-0.8,-0.8) 11(-1.6,-0.8) 12(-1.6,0)
Top Layer:
  region: -1.35,0.55 -1.93,0.55 -1.93,0.8 -1.85,0.8 -1.85,1.05 -1.35,1.05
Top Overlay:
  lines w0.12: -2.395,0.55 -2.395,1.395 -1.55,1.395 ; -0.8,-1.175 -0.8,-1.225 -2.225,-1.225 -2.225,1.225 -0.8,1.225 -0.8,1.175 ; 0.8,-1.175 0.8,-1.225 2.225,-1.225 2.225,1.225 0.8,1.225 0.8,1.175 ; -2.175,-1.175 2.175,-1.175 2.175,1.175 -2.175,1.175 -2.175,-1.175
M14-Top Assembly:
  circle w0.01: c1.5,0 r0.1
  circle w0.01: c-1.5,0 r0.2
  lines w0.01: -0.8,-1.175 -0.8,-1.225 -2.225,-1.225 -2.225,1.225 -0.8,1.225 -0.8,1.175 ; 0.8,-1.175 0.8,-1.225 2.225,-1.225 2.225,1.225 0.8,1.225 0.8,1.175 ; -2.175,-1.175 -2.175,1.175 2.175,1.175 2.175,-1.175 -2.175,-1.175 ; -2,-0.875 ccw(c-1.875,-0.875) -1.875,-1 1.875,-1 ccw(c1.875,-0.875) 2,-0.875 2,1.225 2,1.875 ccw(c1.875,1.875) 1.875,2 -1.875,2 ccw(c-1.875,1.875) -2,1.875 -2,-0.875 ; -1.93,0.55 -1.35,0.55 -1.35,1.05 -1.85,1.05 -1.85,0.8 -1.93,0.8 -1.93,0.55
  text "1" at -1.655,0.64 h0.5
  text "'.Designator'" at -2,-0.5 h0.75
  text "PROTECTIVE LINE" at -1.25,1.75 h0.3
  text "RESTRICTED ZONE H = 1mm" at -1.825,1.45 h0.3
M16-Top Courtyard:
  lines w0.01: -2.425,-1.425 -2.425,1.425 -2.2,1.425 -2.2,2.2 2.2,2.2 2.2,1.425 2.425,1.425 2.425,-1.425 -2.425,-1.425
  text "RESTRICTED ZONE H = 1mm" at -1.825,1.45 h0.3
  text "PROTECTIVE LINE" at -1.25,1.75 h0.3
3D body: height 1.08, standoff 1.04, extent -2,-1 2,2
3D body: height 1.1, standoff 0, extent -2.225,-1.225 2.225,1.225
3D body "vl53l0x.STEP": height 1.04, standoff 0, extent -2.2,-1.2 2.2,1.2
